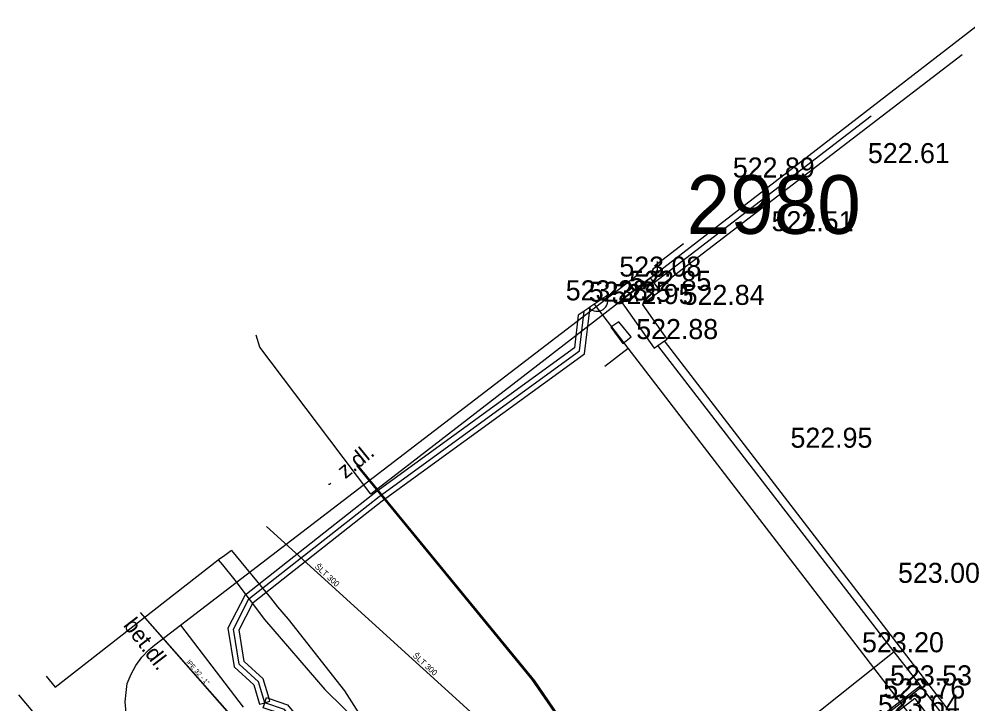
# Model space of a CAD drawing. Extents: x -668867 to -667827, y -1131943 to -1131019.
# Drawn here: x -668692.65 to -668657.13, y -1131187.83 to -1131162.21 of the extents above; entities that cross this region are included whole.
import ezdxf

# ---------------------------------------------------------------- set-up
doc = ezdxf.new("R2010")
doc.units = 0
for name, color, linetype in [('G_Bod_tecka', 7, 'Continuous'), ('G_Bod_vyska', 7, 'Continuous'), ('G_Bodove_pole', 7, 'Continuous'), ('G_Breh_Teren', 7, 'Continuous'), ('G_Cesty_Schody', 7, 'Continuous'), ('G_Objekty_technicke', 7, 'Continuous'), ('G_Plochy_zpevnene', 7, 'Continuous'), ('G_Ploty', 7, 'Continuous'), ('G_Popisy_povrchu', 7, 'Continuous'), ('G_Z_CHRANICKA-TEPLOVOD_kotovane', 7, 'Continuous'), ('G_Z_ELsilove_podz_kotovane', 7, 'Continuous'), ('G_Z_PLYNY_podz_geodeticky', 7, 'Continuous'), ('G_Z_SPOJE_podz_geodeticky', 7, 'Continuous'), ('G_Z_SPOJE_podz_kotovane', 7, 'Continuous'), ('G_Z_SPOJE_podz_priblizne', 7, 'Continuous'), ('G_Z_SPOJE_podz_zahozene', 7, 'Continuous'), ('G_Z_VODA_podz_kotovane', 7, 'Continuous'), ('Vrstva 1', 7, 'Continuous'), ('Vrstva 11', 7, 'Continuous'), ('Vrstva 17', 7, 'Continuous'), ('Vrstva 26', 7, 'Continuous'), ('Vrstva 4', 7, 'Continuous')]:
    doc.layers.add(name, color=color, linetype=linetype)

msp = doc.modelspace()

# ---------------------------------------------------------------- linework, layer by layer
at = {"layer": 'G_Bod_tecka'}
for p, q in [((-668659.73, -1131167.61), (-668659.73, -1131167.61)), ((-668663.35, -1131170.16), (-668663.35, -1131170.16)), ((-668668.97, -1131171.86), (-668668.97, -1131171.86)), ((-668668.63, -1131172.39), (-668668.63, -1131172.39)), ((-668670.13, -1131172.8), (-668670.13, -1131172.8)), ((-668669.29, -1131172.89), (-668669.29, -1131172.89)), ((-668666.63, -1131172.92), (-668666.63, -1131172.92)), ((-668668.36, -1131174.2), (-668668.36, -1131174.2)), ((-668662.58, -1131178.27), (-668662.58, -1131178.27)), ((-668658.51, -1131183.33), (-668658.51, -1131183.33)), ((-668659.88, -1131185.93), (-668659.88, -1131185.93)), ((-668658.85, -1131187.17), (-668658.85, -1131187.17)), ((-668659.09, -1131187.66), (-668659.09, -1131187.66))]:
    msp.add_line(p, q, dxfattribs=at)
at = {"layer": 'G_Bodove_pole'}
msp.add_line((-668670.625, -1131172.578), (-668671.298, -1131173.035), dxfattribs=at)
msp.add_arc((-668671, -1131172.75), 0.412, 223.6959, 24.6142, dxfattribs=at)
at = {"layer": 'G_Breh_Teren'}
msp.add_line((-668659.86, -1131185.91), (-668677.29, -1131199.77), dxfattribs=at)
at = {"layer": 'G_Cesty_Schody'}
for points in [[(-668670.48, -1131173.76), (-668670.02, -1131174.36), (-668669.71, -1131174.12), (-668670.17, -1131173.55), (-668670.48, -1131173.76)], [(-668688.04, -1131186.11), (-668687.78, -1131185.84), (-668687.56, -1131185.65), (-668686.6, -1131184.91)], [(-668684.41, -1131194.44), (-668687.09, -1131191.19), (-668688.39, -1131189.55), (-668688.46, -1131189.27), (-668688.5, -1131188.98), (-668688.55, -1131188.69), (-668688.62, -1131188.34), (-668688.67, -1131187.79), (-668688.63, -1131187.44), (-668688.59, -1131187.1), (-668688.45, -1131186.75), (-668688.27, -1131186.42), (-668688.04, -1131186.11)]]:
    msp.add_lwpolyline(points, dxfattribs=at)
at = {"layer": 'G_Objekty_technicke'}
msp.add_line((-668668.73, -1131171.68), (-668668.73, -1131171.292), dxfattribs=at)
for radius in [0.19, 0.05]:
    msp.add_circle((-668668.73, -1131171.68), radius, dxfattribs=at)
at = {"layer": 'G_Plochy_zpevnene'}
for p, q in [((-668671.57, -1131173.41), (-668669.49, -1131171.808)), ((-668686.6, -1131184.91), (-668671.57, -1131173.41)), ((-668686.6, -1131184.91), (-668684.25, -1131187.98)), ((-668659.09, -1131187.66), (-668649.58, -1131199.79))]:
    msp.add_line(p, q, dxfattribs=at)
for points in [[(-668688.73, -1131192.19), (-668692.647, -1131187.519)], [(-668659.09, -1131187.66), (-668662.12, -1131190), (-668662.04, -1131190.13), (-668661.93, -1131190.3)]]:
    msp.add_lwpolyline(points, dxfattribs=at)
at = {"layer": 'G_Ploty'}
for p, q in [((-668668.71, -1131172.28), (-668657.309, -1131163.544)), ((-668660.719, -1131165.857), (-668668.85, -1131172.09)), ((-668659.86, -1131185.91), (-668668.72, -1131174.44)), ((-668658.87, -1131187.18), (-668659.86, -1131185.91)), ((-668674.43, -1131199.3), (-668658.84, -1131187.23)), ((-668658.84, -1131187.23), (-668658.87, -1131187.18)), ((-668650.32, -1131198.25), (-668658.84, -1131187.23))]:
    msp.add_line(p, q, dxfattribs=at)
for points in [[(-668668.72, -1131174.44), (-668668.47, -1131174.27), (-668668.36, -1131174.2), (-668669.29, -1131172.89), (-668668.63, -1131172.39), (-668668.71, -1131172.28), (-668668.85, -1131172.09), (-668668.89, -1131172.04), (-668668.99, -1131171.91), (-668670.11, -1131172.76), (-668668.85, -1131174.54), (-668668.72, -1131174.44)], [(-668655.14, -1131191.58), (-668668.47, -1131174.27)], [(-668677.64, -1131201.72), (-668658.87, -1131187.18)]]:
    msp.add_lwpolyline(points, dxfattribs=at)
at = {"layer": 'G_Z_CHRANICKA-TEPLOVOD_kotovane'}
msp.add_line((-668671.255, -1131173.005), (-668671.693, -1131173.303), dxfattribs=at)
msp.add_lwpolyline([(-668671.693, -1131173.303), (-668671.838, -1131174.53), (-668679.28, -1131179.94), (-668680.103, -1131180.583), (-668684.188, -1131183.8), (-668684.818, -1131185.027), (-668684.587, -1131186.48), (-668683.855, -1131187.151), (-668683.631, -1131187.879), (-668683.44, -1131187.82), (-668683.249, -1131187.761), (-668683.279, -1131187.663), (-668683.505, -1131186.929), (-668684.213, -1131186.28), (-668684.402, -1131185.093), (-668683.872, -1131184.06), (-668679.857, -1131180.897), (-668679.04, -1131180.26), (-668671.462, -1131174.75), (-668671.255, -1131173.005)], dxfattribs=at)
msp.add_lwpolyline([(-668683.376, -1131187.63), (-668683.279, -1131187.663), (-668682.582, -1131187.899), (-668680.05, -1131190.968), (-668675.294, -1131196.035), (-668674.79, -1131197.063), (-668674.78, -1131199.43), (-668674.54, -1131199.61), (-668674.78, -1131199.93), (-668675.18, -1131199.63), (-668675.19, -1131197.157), (-668675.626, -1131196.265), (-668680.35, -1131191.232), (-668682.818, -1131188.241), (-668683.504, -1131188.01), (-668683.44, -1131187.82)], close=True, dxfattribs=at)
at = {"layer": 'G_Z_ELsilove_podz_kotovane'}
for points in [[(-668668.84, -1131171.46), (-668667.748, -1131170.627)], [(-668674.66, -1131199.77), (-668674.98, -1131199.53), (-668674.99, -1131197.11), (-668675.46, -1131196.15), (-668680.2, -1131191.1), (-668682.7, -1131188.07), (-668683.44, -1131187.82), (-668683.68, -1131187.04), (-668684.4, -1131186.38), (-668684.61, -1131185.06), (-668684.03, -1131183.93), (-668679.98, -1131180.74), (-668679.16, -1131180.1), (-668671.65, -1131174.64), (-668671.474, -1131173.154)]]:
    msp.add_lwpolyline(points, dxfattribs=at)
at = {"layer": 'G_Z_PLYNY_podz_geodeticky'}
for points in [[(-668680.966, -1131179.594), (-668681.02, -1131179.65), (-668681.048, -1131179.649)], [(-668684.686, -1131182.118), (-668684.93, -1131182.3), (-668685.14, -1131182.44)], [(-668691.63, -1131186.829), (-668691.29, -1131187.24), (-668685.18, -1131182.47)], [(-668685.14, -1131182.44), (-668685.17, -1131182.46), (-668685.18, -1131182.47), (-668685.02, -1131182.66)], [(-668685.02, -1131182.66), (-668684.56, -1131183.23), (-668683.45, -1131184.7), (-668681.19, -1131187.32), (-668679, -1131189.47), (-668678.8, -1131189.69), (-668666.63, -1131201.47), (-668659.11, -1131209.53), (-668653.56, -1131215.8), (-668644.79, -1131226.23), (-668644.57, -1131226.51)]]:
    msp.add_lwpolyline(points, dxfattribs=at)
at = {"layer": 'G_Z_SPOJE_podz_geodeticky'}
for points in [[(-668669.83, -1131174.54), (-668671.093, -1131172.896)], [(-668670.7, -1131175.22), (-668669.83, -1131174.54)], [(-668585.93, -1131283.38), (-668602.83, -1131261.2), (-668660.25, -1131187), (-668669.83, -1131174.54)], [(-668684.68, -1131182.114), (-668683.22, -1131183.89), (-668682.96, -1131184.23), (-668682.56, -1131184.69), (-668680.45, -1131187.38), (-668678.18, -1131190.94)]]:
    msp.add_lwpolyline(points, dxfattribs=at)
at = {"layer": 'G_Z_SPOJE_podz_kotovane'}
for points in [[(-668589.47, -1131129.67), (-668592.11, -1131130.55), (-668593.15, -1131129.39), (-668596.92, -1131125.3), (-668597.48, -1131122.62), (-668586.29, -1131113.38), (-668581.92, -1131111.18), (-668581.23, -1131108.4), (-668580.77, -1131106.33), (-668583.38, -1131105.79), (-668679.46, -1131180.01), (-668681, -1131177.98), (-668683.63, -1131174.5), (-668683.76, -1131174.05)], [(-668669.83, -1131174.54), (-668671.093, -1131172.896)], [(-668670.7, -1131175.22), (-668669.83, -1131174.54)], [(-668585.93, -1131283.38), (-668602.83, -1131261.2), (-668660.25, -1131187), (-668669.83, -1131174.54)], [(-668680.003, -1131178.941), (-668673.44, -1131186.94), (-668666.56, -1131196.91), (-668659.78, -1131205.9), (-668656.26, -1131209.87), (-668640.18, -1131228.99)]]:
    msp.add_lwpolyline(points, dxfattribs=at)
at = {"layer": 'G_Z_SPOJE_podz_priblizne'}
for points in [[(-668669.83, -1131174.54), (-668671.093, -1131172.896)], [(-668670.7, -1131175.22), (-668669.83, -1131174.54)], [(-668585.93, -1131283.38), (-668602.83, -1131261.2), (-668660.25, -1131187), (-668669.83, -1131174.54)]]:
    msp.add_lwpolyline(points, dxfattribs=at)
at = {"layer": 'G_Z_SPOJE_podz_zahozene'}
for p, q in [((-668680.003, -1131178.941), (-668673.44, -1131186.94)), ((-668679.973, -1131178.92), (-668679.92, -1131178.99)), ((-668679.92, -1131178.99), (-668673.34, -1131187)), ((-668673.44, -1131186.94), (-668667.77, -1131195.16)), ((-668673.34, -1131187), (-668667.77, -1131195.16))]:
    msp.add_line(p, q, dxfattribs=at)
at = {"layer": 'G_Z_VODA_podz_kotovane'}
msp.add_line((-668688.113, -1131184.443), (-668684.68, -1131188.34), dxfattribs=at)
msp.add_lwpolyline([(-668683.369, -1131181.224), (-668649.8, -1131211.72), (-668646.34, -1131215.79), (-668601.09, -1131269.33), (-668550.43, -1131331.42), (-668550.07, -1131333.92), (-668545.5, -1131360.28), (-668544.8, -1131361.58), (-668534.06, -1131374.68), (-668512.85, -1131400.04), (-668473.31, -1131428.57), (-668463.03, -1131434.08), (-668452.78, -1131440.2), (-668452.76, -1131440.21)], dxfattribs=at)
at = {"layer": 'Vrstva 1'}
msp.add_line((-668668.84, -1131171.46), (-668668.84, -1131171.46), dxfattribs=at)
at = {"layer": 'Vrstva 11'}
for points in [[(-668680, -1131178.939), (-668673.444, -1131186.942), (-668666.555, -1131196.91), (-668659.781, -1131205.895), (-668656.257, -1131209.872), (-668640.181, -1131228.994), (-668629.682, -1131242.6)], [(-668680, -1131178.939), (-668673.444, -1131186.942), (-668666.555, -1131196.91), (-668659.781, -1131205.895), (-668656.257, -1131209.872), (-668640.181, -1131228.994), (-668629.682, -1131242.6)], [(-668679.976, -1131178.923), (-668679.924, -1131178.992), (-668673.34, -1131186.995), (-668665.298, -1131198.772), (-668659.351, -1131206.563), (-668655.387, -1131210.812), (-668652.202, -1131214.849), (-668645.618, -1131222.498)], [(-668679.976, -1131178.923), (-668679.924, -1131178.992), (-668673.34, -1131186.995), (-668665.298, -1131198.772), (-668659.351, -1131206.563), (-668655.387, -1131210.812), (-668652.202, -1131214.849), (-668645.618, -1131222.498)], [(-668679.976, -1131178.923), (-668679.924, -1131178.992), (-668673.34, -1131186.995), (-668665.298, -1131198.772), (-668659.351, -1131206.563), (-668655.387, -1131210.812), (-668652.202, -1131214.849), (-668645.618, -1131222.498)]]:
    msp.add_lwpolyline(points, dxfattribs=at)
at = {"layer": 'Vrstva 17'}
msp.add_line((-668668.84, -1131171.46), (-668667.748, -1131170.627), dxfattribs=at)
at = {"layer": 'Vrstva 26'}
msp.add_line((-668688.111, -1131184.442), (-668684.676, -1131188.34), dxfattribs=at)
msp.add_lwpolyline([(-668683.369, -1131181.224), (-668649.798, -1131211.717), (-668646.336, -1131215.786), (-668601.09, -1131269.326), (-668550.43, -1131331.42), (-668550.07, -1131333.92), (-668545.496, -1131360.279), (-668544.8, -1131361.58), (-668534.06, -1131374.68), (-668512.85, -1131400.04), (-668473.31, -1131428.57), (-668463.033, -1131434.082), (-668452.779, -1131440.199), (-668452.76, -1131440.21)], dxfattribs=at)

# ---------------------------------------------------------------- texts
at = {"layer": 'G_Bod_vyska'}
for s, p in [('522.61', (-668660.846, -1131167.61)), ('522.89', (-668665.906, -1131168.15)), ('522.51', (-668664.452, -1131170.16)), ('523.08', (-668670.156, -1131171.86)), ('522.85', (-668669.784, -1131172.39)), ('523.28', (-668672.164, -1131172.75)), ('523.35', (-668671.301, -1131172.8)), ('522.95', (-668670.446, -1131172.89)), ('522.84', (-668667.784, -1131172.92)), ('522.88', (-668669.524, -1131174.2)), ('522.95', (-668663.746, -1131178.27)), ('523.00', (-668659.717, -1131183.33)), ('523.20', (-668661.066, -1131185.93)), ('523.53', (-668660.014, -1131187.17)), ('523.76', (-668660.268, -1131187.66)), ('523.64', (-668660.468, -1131188.27))]:
    msp.add_text(s, height=0.75, dxfattribs=at).set_placement(p)
at = {"layer": 'G_Popisy_povrchu'}
for s, rotation, p in [('z.dl.', 39.1955, (-668680.421, -1131179.457)), ('bet.dl.', 307.4338, (-668688.764, -1131184.925))]:
    msp.add_text(s, height=0.6, rotation=rotation, dxfattribs=at).set_placement(p)
at = {"layer": 'Vrstva 4'}
msp.add_text('2980', height=2.1939, dxfattribs=at).set_placement((-668667.637, -1131170.259))
for s, height, rotation, p in [('ŠLT 300', 0.2194, 317.7803, (-668681.582, -1131182.751)), ('ŠLT 300', 0.2194, 317.7803, (-668677.916, -1131186.081)), ('lPE 32 - 1"', 0.17551, 311.368, (-668686.383, -1131186.31))]:
    msp.add_text(s, height=height, rotation=rotation, dxfattribs=at).set_placement(p)

doc.saveas('drawing.dxf')
